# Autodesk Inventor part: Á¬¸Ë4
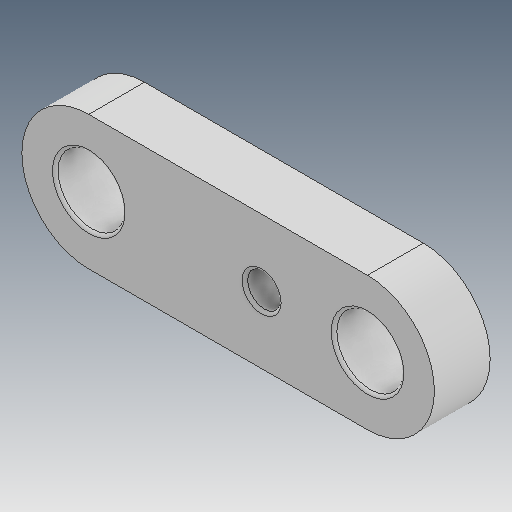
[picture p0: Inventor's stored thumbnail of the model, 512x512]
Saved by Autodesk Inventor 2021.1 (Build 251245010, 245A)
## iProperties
Created: 2014-12
Part Number: Á¬¸Ë4
Material: Ogólny
Document SubType Name: Modeling
Designer: user
Density: 1 g/cm^3
Appearance: Domyślna
Author: user
Revision Number: ÈÎºÎ
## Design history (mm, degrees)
feature "ÊäÈë1"
node "Bryła1"
